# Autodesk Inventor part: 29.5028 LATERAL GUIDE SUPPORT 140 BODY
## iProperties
Created: 2007-07
Part Number: 29.5028 LATERAL GUIDE SUPPORT 140 BODY
Document SubType Name: Modeling
Designer: Andy Moles
Material: ABS Plastic
Mass: 42.2452 g
Surface Area: 188.341 cm^2
Volume: 39.854 cm^3
Density: 1.06 g/cm^3
Author: Andy Moles
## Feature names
1. Base1
